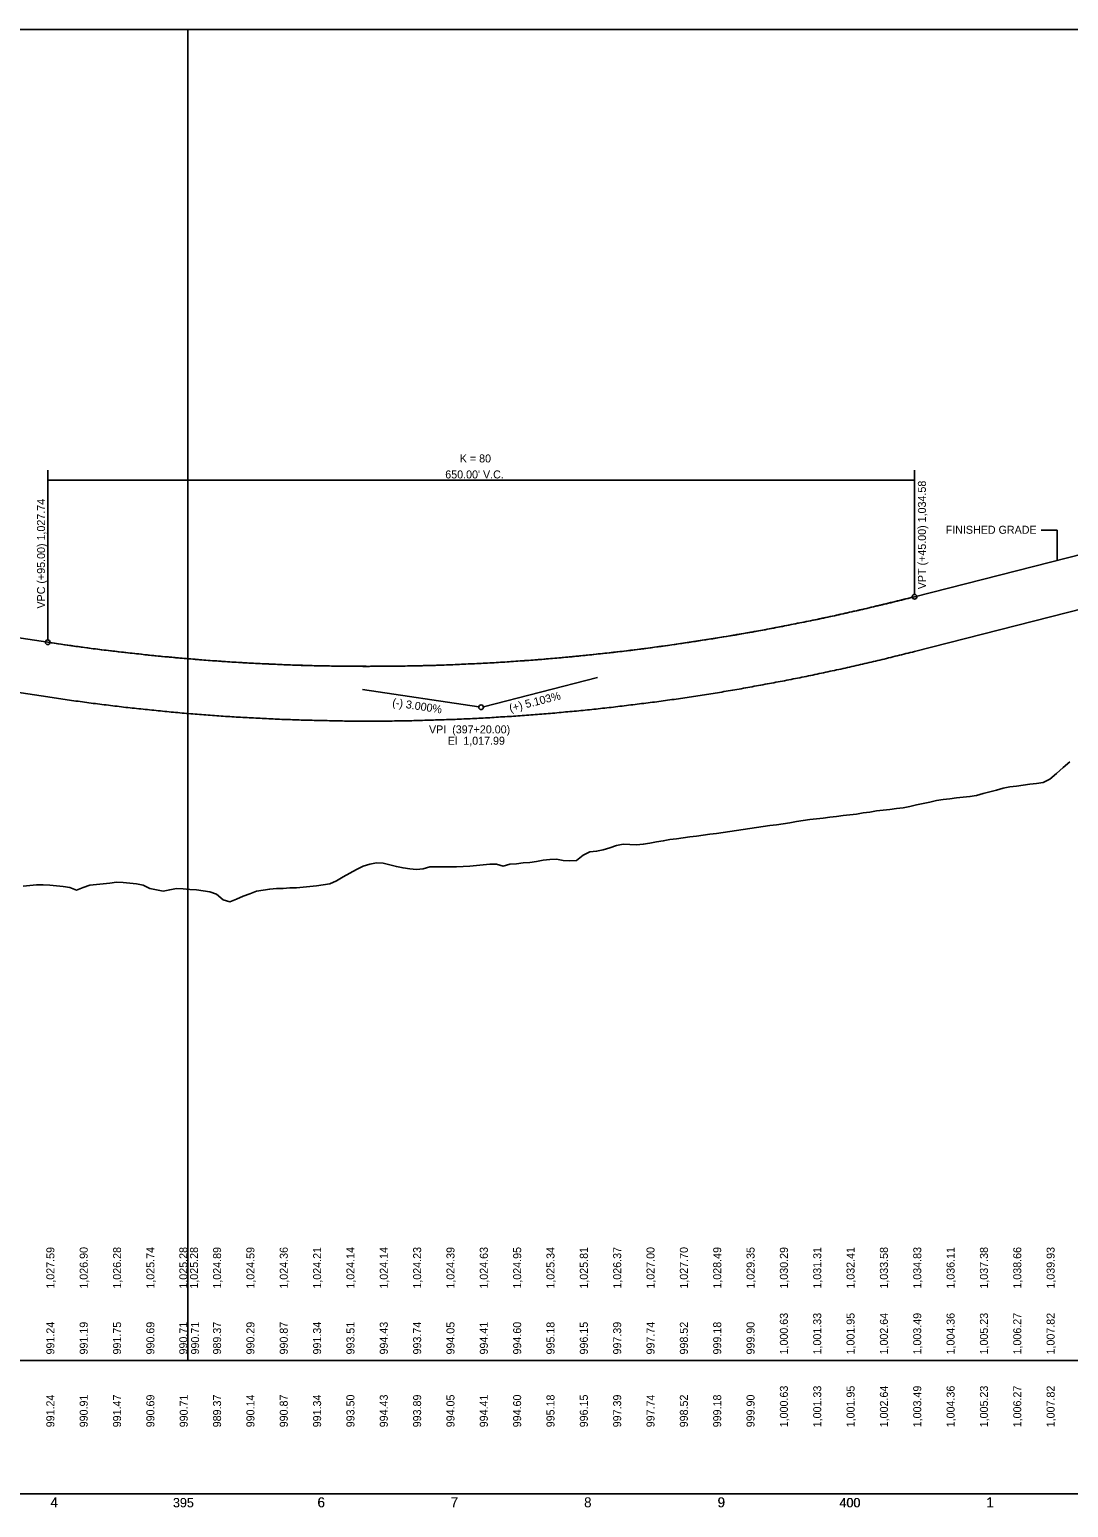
# Model space of a CAD drawing. Extents: x 150 to 16976893, y 3102 to 12559827.
# Drawn here: x 16973774 to 16974553, y 12558429 to 12559538 of the extents above; entities that cross this region are included whole.
import ezdxf

# ---------------------------------------------------------------- set-up
doc = ezdxf.new("R2010")
doc.units = 0
for name, color, linetype in [('Default', 7, 'Continuous'), ('Level 56', 7, 'Continuous'), ('RD_DDB_GradeTX', 7, 'Continuous'), ('RD_DDB_PI', 7, 'Continuous'), ('RD_DDB_Pr_Tx', 7, 'Continuous'), ('RD_DDB_Profile_EX', 7, 'Continuous'), ('RD_DDB_StaTX', 7, 'Continuous'), ('RD_DDB_StripGrade_EX', 7, 'Continuous'), ('RD_GPK_Profile_Cell', 7, 'Continuous'), ('RD_HC_TX_Sta20', 7, 'Continuous'), ('RD_PD_Bridge', 7, 'Continuous'), ('RD_XS_Misc_Line', 7, 'Continuous')]:
    doc.layers.add(name, color=color, linetype=linetype)

msp = doc.modelspace()

# ---------------------------------------------------------------- linework, layer by layer
at = {"layer": 'Default'}
msp.add_line((16973373.6, 12559140.2), (16973787.9, 12559078), dxfattribs=at)
for points in [[(16972392.9, 12558539.3), (16973892.9, 12558539.3), (16973892.9, 12559537.5), (16972392.9, 12559537.5)], [(16973892.9, 12558539.3), (16975392.9, 12558539.3), (16975392.9, 12559537.5), (16973892.9, 12559537.5)]]:
    msp.add_lwpolyline(points, close=True, dxfattribs=at)
msp.add_open_spline([(16973787.9, 12559078), (16974112.9, 12559029.3), (16974437.9, 12559112.2)], degree=2, dxfattribs=at)
at = {"layer": 'RD_DDB_PI'}
for p, q in [((16974200.1, 12559051.5), (16974114.6, 12559029.7)), ((16974023.9, 12559042.6), (16974111.2, 12559029.5))]:
    msp.add_line(p, q, dxfattribs=at)
msp.add_circle((16974112.9, 12559029.3), 1.75, dxfattribs=at)
at = {"layer": 'RD_DDB_Pr_Tx'}
for p, q in [((16974532.9, 12559162.2), (16974544.7, 12559162.2)), ((16974544.7, 12559162.2), (16974544.7, 12559139.4))]:
    msp.add_line(p, q, dxfattribs=at)
at = {"layer": 'RD_DDB_Profile_EX'}
for points in [[(16974259.4, 12558930.7), (16974264.4, 12558931.4), (16974269.4, 12558932.1), (16974274.4, 12558932.7), (16974279.4, 12558933.4), (16974284.4, 12558934.1), (16974289.4, 12558934.7), (16974294.4, 12558935.4), (16974299.4, 12558936.1), (16974304.4, 12558936.8), (16974309.4, 12558937.5), (16974314.4, 12558938.3), (16974319.4, 12558939), (16974324.4, 12558939.8), (16974329.4, 12558940.5), (16974334.4, 12558941.2), (16974339.4, 12558941.9), (16974344.4, 12558942.7), (16974349.4, 12558943.6), (16974354.4, 12558944.4), (16974359.4, 12558945.1), (16974364.4, 12558945.5), (16974369.4, 12558946.2), (16974374.4, 12558946.8), (16974379.4, 12558947.4), (16974384.4, 12558948), (16974389.4, 12558948.6), (16974394.4, 12558949.2), (16974399.4, 12558950), (16974404.4, 12558950.7), (16974409.4, 12558951.5), (16974414.4, 12558952.1), (16974419.4, 12558952.7), (16974424.4, 12558953.3), (16974429.4, 12558953.9), (16974434.4, 12558954.9), (16974439.4, 12558956), (16974444.4, 12558957.1), (16974449.4, 12558958.2), (16974454.4, 12558959.3), (16974459.4, 12558960.2), (16974464.4, 12558960.7), (16974469.4, 12558961.3), (16974474.4, 12558961.8), (16974479.4, 12558962.3), (16974484.4, 12558963.2), (16974489.4, 12558964.5), (16974494.4, 12558965.9), (16974499.4, 12558967.2), (16974504.4, 12558968.5), (16974509.4, 12558969.6), (16974514.4, 12558970.2), (16974519.4, 12558970.9), (16974524.4, 12558971.5), (16974529.4, 12558972.2), (16974534.4, 12558972.9), (16974539.4, 12558975.4), (16974544.4, 12558979.7), (16974549.4, 12558984.1), (16974554.4, 12558988.4)], [(16973769.4, 12558895.2), (16973774.4, 12558895.7), (16973779.4, 12558896.2), (16973784.4, 12558896.1), (16973789.4, 12558895.8), (16973794.4, 12558895.4), (16973799.4, 12558894.8), (16973804.4, 12558894.1), (16973809.4, 12558892.2), (16973814.4, 12558894.1), (16973819.4, 12558895.8), (16973824.4, 12558896.4), (16973829.4, 12558897), (16973834.4, 12558897.5), (16973839.4, 12558898.1), (16973844.4, 12558898), (16973849.4, 12558897.5), (16973854.4, 12558897), (16973859.4, 12558895.8), (16973864.4, 12558893.5), (16973869.4, 12558892.4), (16973874.4, 12558891.5), (16973879.4, 12558892.5), (16973884.4, 12558893.3), (16973889.4, 12558893.1), (16973894.4, 12558892.7), (16973899.4, 12558892.3), (16973904.4, 12558891.6), (16973909.4, 12558890.9), (16973914.4, 12558889.1), (16973919.4, 12558884.9), (16973924.4, 12558883.5), (16973929.4, 12558885.5), (16973934.4, 12558887.6), (16973939.4, 12558889.5), (16973944.4, 12558891.3), (16973949.4, 12558892.1), (16973954.4, 12558893), (16973959.4, 12558893.3), (16973964.4, 12558893.5), (16973969.4, 12558893.8), (16973974.4, 12558893.8), (16973979.4, 12558894.4), (16973984.4, 12558895), (16973989.4, 12558895.5), (16973994.4, 12558896.2), (16973999.4, 12558897), (16974004.4, 12558899.2), (16974009.4, 12558902.1), (16974014.4, 12558904.9), (16974019.4, 12558907.7), (16974024.4, 12558910.2), (16974029.4, 12558911.5), (16974034.4, 12558912.5), (16974039.4, 12558912.3), (16974044.4, 12558911.1), (16974049.4, 12558909.8), (16974054.4, 12558908.8), (16974059.4, 12558908.2), (16974064.4, 12558907.6), (16974069.4, 12558908.2), (16974074.4, 12558909.5), (16974079.4, 12558909.5), (16974084.4, 12558909.5), (16974089.4, 12558909.5), (16974094.4, 12558909.6), (16974099.4, 12558909.8), (16974104.4, 12558910.1), (16974109.4, 12558910.5), (16974114.4, 12558911.2), (16974119.4, 12558911.5), (16974124.4, 12558911.7), (16974129.4, 12558910.1), (16974134.4, 12558911.5), (16974139.4, 12558911.9), (16974144.4, 12558912.5), (16974149.4, 12558912.9), (16974154.4, 12558913.5), (16974159.4, 12558914.5), (16974164.4, 12558915.1), (16974169.4, 12558915.3), (16974174.4, 12558914.4), (16974179.4, 12558914.1), (16974184.4, 12558914.4), (16974189.4, 12558918.3), (16974194.4, 12558920.8), (16974199.4, 12558921.3), (16974204.4, 12558922.4), (16974209.4, 12558923.9), (16974214.4, 12558925.5), (16974219.4, 12558926.6), (16974224.4, 12558926.3), (16974229.4, 12558926), (16974234.4, 12558926.5), (16974239.4, 12558927.4), (16974244.4, 12558928.3), (16974249.4, 12558929.1), (16974254.4, 12558930), (16974259.4, 12558930.7)]]:
    msp.add_lwpolyline(points, dxfattribs=at)
at = {"layer": 'RD_GPK_Profile_Cell'}
msp.add_line((16972208.1, 12558439.3), (16976677.1, 12558439.3), dxfattribs=at)
at = {"layer": 'RD_HC_TX_Sta20'}
for p, q in [((16973787.9, 12559207.2), (16973787.9, 12559079.8)), ((16974437.9, 12559207.2), (16974437.9, 12559113.9)), ((16973787.9, 12559199.7), (16974437.9, 12559199.7))]:
    msp.add_line(p, q, dxfattribs=at)
for centre in [(16974437.9, 12559112.2), (16973787.9, 12559078)]:
    msp.add_circle(centre, 1.75, dxfattribs=at)
at = {"layer": 'RD_PD_Bridge'}
for p, q in [((16974437.9, 12559071.1), (16974597.9, 12559112)), ((16973727.9, 12559046), (16973787.9, 12559037))]:
    msp.add_line(p, q, dxfattribs=at)
msp.add_spline([(16973787.9, 12559037), (16973800.9, 12559035.1), (16973813.9, 12559033.3), (16973826.9, 12559031.6), (16973839.9, 12559030), (16973852.9, 12559028.5), (16973865.9, 12559027.2), (16973878.9, 12559025.9), (16973891.9, 12559024.7), (16973904.9, 12559023.7), (16973917.9, 12559022.7), (16973930.9, 12559021.9), (16973943.9, 12559021.2), (16973956.9, 12559020.5), (16973969.9, 12559020), (16973982.9, 12559019.6), (16973995.9, 12559019.3), (16974008.9, 12559019), (16974021.9, 12559018.9), (16974034.9, 12559018.9), (16974047.9, 12559019), (16974060.9, 12559019.2), (16974073.9, 12559019.6), (16974086.9, 12559020), (16974099.9, 12559020.5), (16974112.9, 12559021.1), (16974125.9, 12559021.9), (16974138.9, 12559022.7), (16974151.9, 12559023.7), (16974164.9, 12559024.7), (16974177.9, 12559025.9), (16974190.9, 12559027.1), (16974203.9, 12559028.5), (16974216.9, 12559030), (16974229.9, 12559031.6), (16974242.9, 12559033.2), (16974255.9, 12559035), (16974268.9, 12559036.9), (16974281.9, 12559038.9), (16974294.9, 12559041), (16974307.9, 12559043.2), (16974320.9, 12559045.6), (16974333.9, 12559048), (16974346.9, 12559050.5), (16974359.9, 12559053.1), (16974372.9, 12559055.9), (16974385.9, 12559058.7), (16974398.9, 12559061.7), (16974411.9, 12559064.7), (16974424.9, 12559067.9), (16974437.9, 12559071.1)], degree=3, dxfattribs=at)
at = {"layer": 'RD_XS_Misc_Line'}
for p, q in [((16974437.9, 12559112.2), (16974597.9, 12559153)), ((16973727.9, 12559087), (16973787.9, 12559078))]:
    msp.add_line(p, q, dxfattribs=at)
msp.add_spline([(16973787.9, 12559078), (16973800.9, 12559076.1), (16973813.9, 12559074.3), (16973826.9, 12559072.6), (16973839.9, 12559071.1), (16973852.9, 12559069.6), (16973865.9, 12559068.2), (16973878.9, 12559066.9), (16973891.9, 12559065.8), (16973904.9, 12559064.7), (16973917.9, 12559063.8), (16973930.9, 12559062.9), (16973943.9, 12559062.2), (16973956.9, 12559061.6), (16973969.9, 12559061), (16973982.9, 12559060.6), (16973995.9, 12559060.3), (16974008.9, 12559060.1), (16974021.9, 12559060), (16974034.9, 12559060), (16974047.9, 12559060.1), (16974060.9, 12559060.3), (16974073.9, 12559060.6), (16974086.9, 12559061), (16974099.9, 12559061.6), (16974112.9, 12559062.2), (16974125.9, 12559062.9), (16974138.9, 12559063.8), (16974151.9, 12559064.7), (16974164.9, 12559065.8), (16974177.9, 12559066.9), (16974190.9, 12559068.2), (16974203.9, 12559069.6), (16974216.9, 12559071), (16974229.9, 12559072.6), (16974242.9, 12559074.3), (16974255.9, 12559076.1), (16974268.9, 12559078), (16974281.9, 12559080), (16974294.9, 12559082.1), (16974307.9, 12559084.3), (16974320.9, 12559086.6), (16974333.9, 12559089), (16974346.9, 12559091.6), (16974359.9, 12559094.2), (16974372.9, 12559096.9), (16974385.9, 12559099.8), (16974398.9, 12559102.7), (16974411.9, 12559105.8), (16974424.9, 12559108.9), (16974437.9, 12559112.2)], degree=3, dxfattribs=at)

# ---------------------------------------------------------------- texts
at = {"layer": 'Level 56'}
for s, p in [('1,027.59', (16973792.9, 12558593.3)), ('1,026.90', (16973817.9, 12558593.3)), ('1,026.28', (16973842.9, 12558593.3)), ('1,025.74', (16973867.9, 12558593.3)), ('1,025.28', (16973892.6, 12558593.3)), ('1,025.28', (16973900.6, 12558593.3)), ('1,024.89', (16973917.9, 12558593.3)), ('1,024.59', (16973942.9, 12558593.3)), ('1,024.36', (16973967.9, 12558593.3)), ('1,024.21', (16973992.9, 12558593.3)), ('1,024.14', (16974017.9, 12558593.3)), ('1,024.14', (16974042.9, 12558593.3)), ('1,024.23', (16974067.9, 12558593.3)), ('1,024.39', (16974092.9, 12558593.3)), ('1,024.63', (16974117.9, 12558593.3)), ('1,024.95', (16974142.9, 12558593.3)), ('1,025.34', (16974167.9, 12558593.3)), ('1,025.81', (16974192.9, 12558593.3)), ('1,026.37', (16974217.9, 12558593.3)), ('1,027.00', (16974242.9, 12558593.3)), ('1,027.70', (16974267.9, 12558593.3)), ('1,028.49', (16974292.9, 12558593.3)), ('1,029.35', (16974317.9, 12558593.3)), ('1,030.29', (16974342.9, 12558593.3)), ('1,031.31', (16974367.9, 12558593.3)), ('1,032.41', (16974392.9, 12558593.3)), ('1,033.58', (16974417.9, 12558593.3)), ('1,034.83', (16974442.9, 12558593.3)), ('1,036.11', (16974467.9, 12558593.3)), ('1,037.38', (16974492.9, 12558593.3)), ('1,038.66', (16974517.9, 12558593.3)), ('1,039.93', (16974542.9, 12558593.3)), ('991.24', (16973792.9, 12558489.3)), ('990.14', (16973942.9, 12558489.3)), ('991.34', (16973992.9, 12558489.3)), ('997.74', (16974242.9, 12558489.3)), ('1,000.63', (16974342.9, 12558489.3)), ('1,001.33', (16974367.9, 12558489.3)), ('1,001.95', (16974392.9, 12558489.3)), ('1,002.64', (16974417.9, 12558489.3)), ('1,003.49', (16974442.9, 12558489.3)), ('1,004.36', (16974467.9, 12558489.3)), ('1,005.23', (16974492.9, 12558489.3)), ('1,006.27', (16974517.9, 12558489.3)), ('1,007.82', (16974542.9, 12558489.3)), ('990.91', (16973817.9, 12558489.3)), ('991.47', (16973842.9, 12558489.3)), ('990.69', (16973867.9, 12558489.3)), ('990.71', (16973892.9, 12558489.3)), ('989.37', (16973917.9, 12558489.3)), ('990.87', (16973967.9, 12558489.3)), ('993.50', (16974017.9, 12558489.3)), ('994.43', (16974042.9, 12558489.3)), ('993.89', (16974067.9, 12558489.3)), ('994.05', (16974092.9, 12558489.3)), ('994.41', (16974117.9, 12558489.3)), ('994.60', (16974142.9, 12558489.3)), ('995.18', (16974167.9, 12558489.3)), ('996.15', (16974192.9, 12558489.3)), ('997.39', (16974217.9, 12558489.3)), ('998.52', (16974267.9, 12558489.3)), ('999.18', (16974292.9, 12558489.3)), ('999.90', (16974317.9, 12558489.3))]:
    msp.add_text(s, height=6, rotation=90, dxfattribs=at).set_placement(p)
at = {"layer": 'RD_DDB_GradeTX'}
for s, rotation, p in [('(-) 3.000%', 351.4692, (16974046, 12559030.2)), ('(+) 5.103%', 14.3136, (16974134.8, 12559025.6))]:
    msp.add_text(s, height=6, rotation=rotation, dxfattribs=at).set_placement(p)
at = {"layer": 'RD_DDB_PI'}
for s, p in [('VPI  (397+20.00)', (16974073.8, 12559009.7)), ('El  1,017.99', (16974087.9, 12559001.2))]:
    msp.add_text(s, height=6, dxfattribs=at).set_placement(p)
at = {"layer": 'RD_DDB_Pr_Tx'}
msp.add_text('FINISHED GRADE', height=6, dxfattribs=at).set_placement((16974461.2, 12559159.4))
at = {"layer": 'RD_DDB_StaTX'}
for s, height, p in [('4', 7.5, (16973789.9, 12558429.3)), ('4', 7.5, (16973790.1, 12558429.3)), ('395', 7, (16973881.8, 12558429.3)), ('395', 7, (16973881.9, 12558429.3)), ('6', 7.5, (16973990.1, 12558429.3)), ('6', 7.5, (16973990.3, 12558429.3)), ('7', 7.5, (16974090, 12558429.3)), ('7', 7.5, (16974090.1, 12558429.3)), ('8', 7.5, (16974190.1, 12558429.3)), ('8', 7.5, (16974190.1, 12558429.3)), ('9', 7.5, (16974290.1, 12558429.3)), ('9', 7.5, (16974290.3, 12558429.3)), ('400', 7, (16974381.5, 12558429.3)), ('400', 7, (16974381.8, 12558429.3)), ('1', 7.5, (16974491.6, 12558429.3)), ('1', 7.5, (16974491.9, 12558429.3))]:
    msp.add_text(s, height=height, dxfattribs=at).set_placement(p)
at = {"layer": 'RD_DDB_StripGrade_EX'}
for s, p in [('1,000.63', (16974342.9, 12558543.9)), ('1,001.33', (16974367.9, 12558543.9)), ('1,001.95', (16974392.9, 12558543.9)), ('1,002.64', (16974417.9, 12558543.9)), ('1,003.49', (16974442.9, 12558543.9)), ('1,004.36', (16974467.9, 12558543.9)), ('1,005.23', (16974492.9, 12558543.9)), ('1,006.27', (16974517.9, 12558543.9)), ('1,007.82', (16974542.9, 12558543.9)), ('991.24', (16973792.9, 12558543.9)), ('991.19', (16973817.9, 12558543.9)), ('991.75', (16973842.9, 12558543.9)), ('990.69', (16973867.9, 12558543.9)), ('990.71', (16973892.6, 12558543.9)), ('990.71', (16973901.4, 12558543.9)), ('989.37', (16973917.9, 12558543.9)), ('990.29', (16973942.9, 12558543.9)), ('990.87', (16973967.9, 12558543.9)), ('991.34', (16973992.9, 12558543.9)), ('993.51', (16974017.9, 12558543.9)), ('994.43', (16974042.9, 12558543.9)), ('993.74', (16974067.9, 12558543.9)), ('994.05', (16974092.9, 12558543.9)), ('994.41', (16974117.9, 12558543.9)), ('994.60', (16974142.9, 12558543.9)), ('995.18', (16974167.9, 12558543.9)), ('996.15', (16974192.9, 12558543.9)), ('997.39', (16974217.9, 12558543.9)), ('997.74', (16974242.9, 12558543.9)), ('998.52', (16974267.9, 12558543.9)), ('999.18', (16974292.9, 12558543.9)), ('999.90', (16974317.9, 12558543.9))]:
    msp.add_text(s, height=6, rotation=90, dxfattribs=at).set_placement(p)
at = {"layer": 'RD_HC_TX_Sta20'}
for s, p in [('K = 80', (16974096.9, 12559212.9)), ("650.00' V.C.", (16974086, 12559200.9))]:
    msp.add_text(s, height=6, dxfattribs=at).set_placement(p)
for s, p in [('VPT (+45.00) 1,034.58', (16974446.4, 12559117.8)), ('VPC (+95.00) 1,027.74', (16973785.9, 12559103.3))]:
    msp.add_text(s, height=6, rotation=90, dxfattribs=at).set_placement(p)

doc.saveas('drawing.dxf')
